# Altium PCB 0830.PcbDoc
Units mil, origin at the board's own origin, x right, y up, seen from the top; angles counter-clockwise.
Board outline 6000 x 4000 mil, 2 copper layers (Top Layer, Bottom Layer); 10 components, 22 nets, 57 pads, 0 vias.
Unrouted connection lines stored in the file: 34.
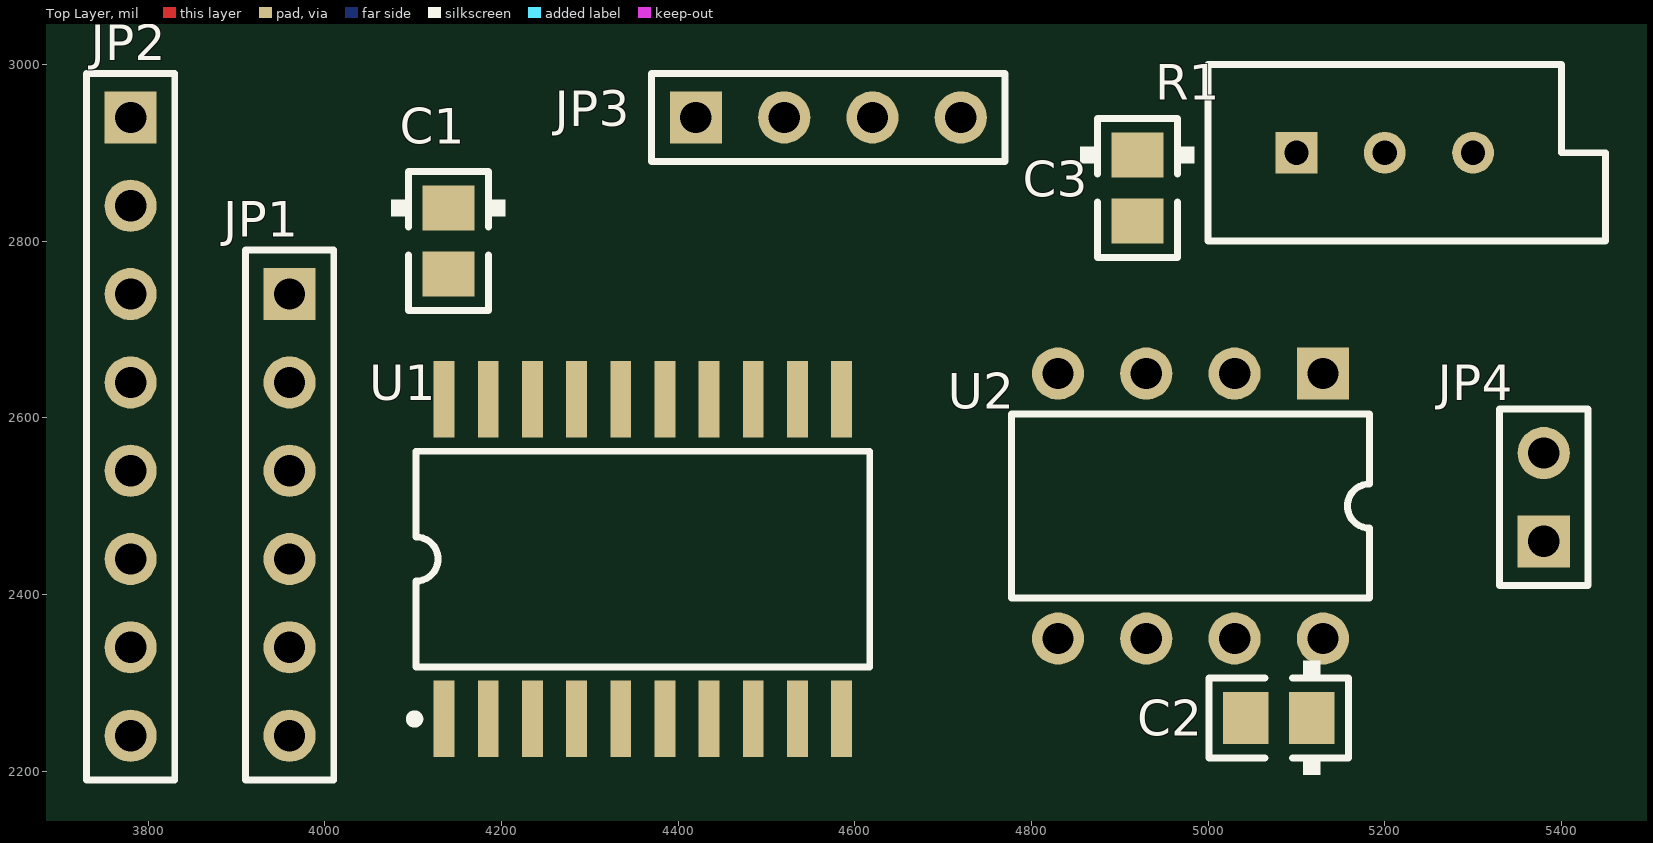
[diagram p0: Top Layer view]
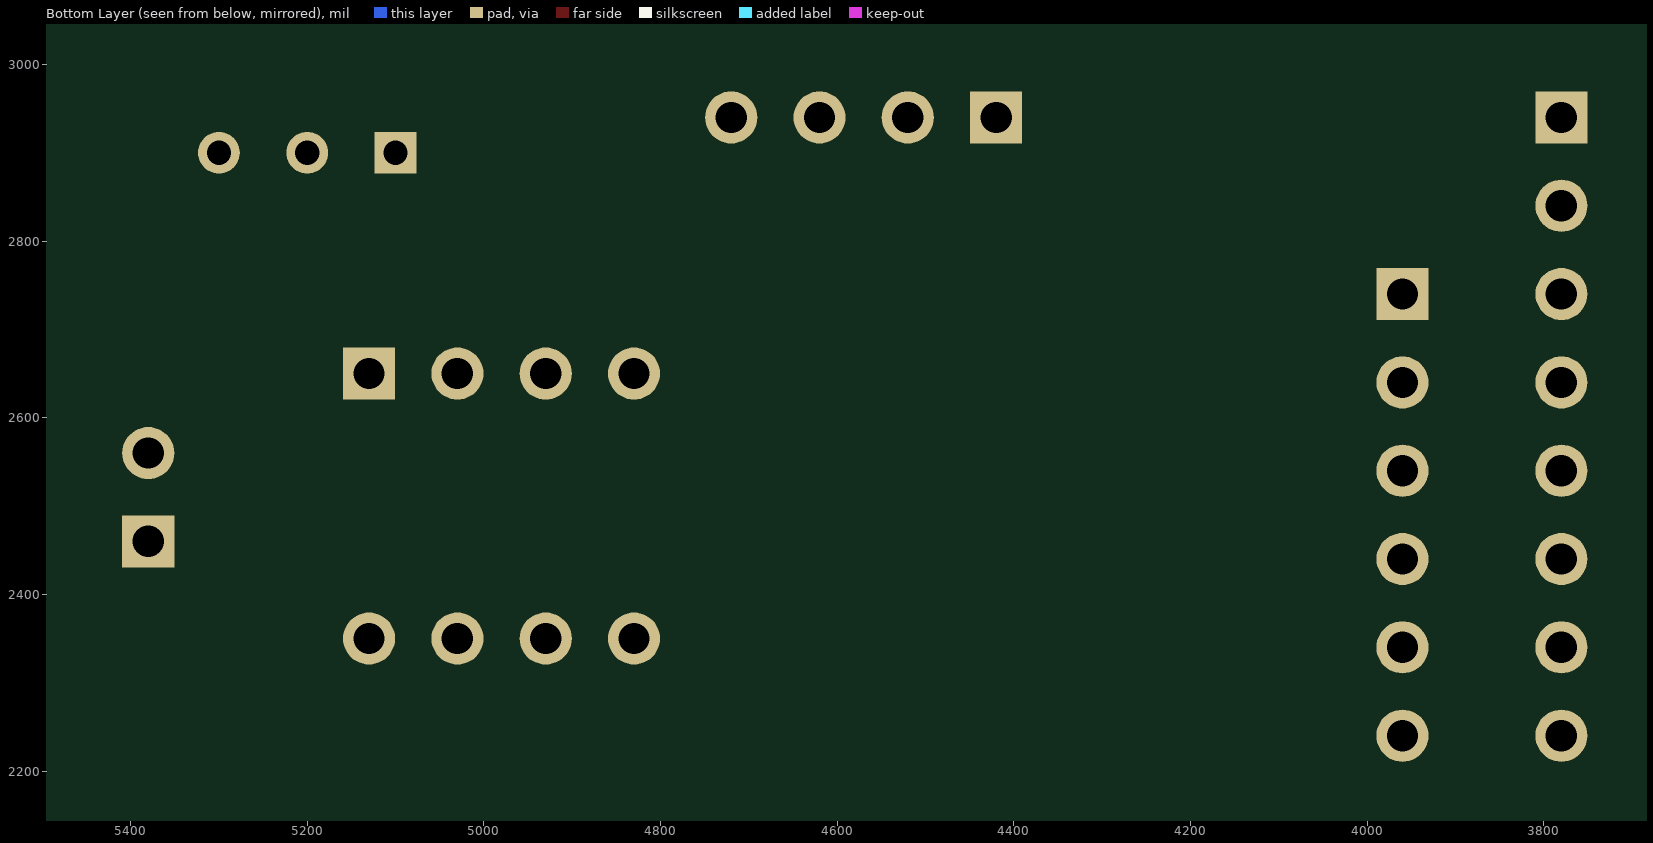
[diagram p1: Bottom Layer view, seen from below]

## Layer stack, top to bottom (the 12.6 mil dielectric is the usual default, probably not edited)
Top Layer: signal copper 1.4
Dielectric: dielectric 12.6, FR-4, Dk 4.8
Bottom Layer: signal copper 1.4

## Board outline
1000,1000 7000,1000 7000,5000 1000,5000

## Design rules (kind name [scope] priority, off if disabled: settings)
Clearance [All] p1: gap=10
ComponentClearance [All] p1: gap=10 collisioncheckmode=0
PolygonConnect [All] p1: connectstyle=Relief reliefconductorwidth=10 reliefentries=4 polygonreliefangle="90 Angle"
RoutingLayers [All] p1: top layer=Horizontal bottom layer=Vertical
RoutingVias [All] p1: holewidth=28 width=50 viastyle="Through Hole" minholewidth=28 minwidth=50 maxholewidth=28 maxwidth=50
SolderMaskExpansion [All] p1: expansion=4
TestPointUsage [All] p1: valid=0 allowmultiple=FALSE
Testpoint [All] p1: side=15 testpointundercomponent=TRUE minsize=40 maxsize=100 preferedsize=60 minholesize=0 maxholesize=40 preferedholesize=32 testpointgrid=1 style=1023 order=1234567890
Width [All] p1: maxlimit=10 minlimit=10 preferedwidth=10
16 further rules are at their usual default settings.

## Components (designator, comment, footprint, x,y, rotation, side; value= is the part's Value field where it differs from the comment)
C1 "Cap" CC2012-0805 4140,2800 r270 top
C2 "Cap" CC2012-0805 5080,2260 r180 top
C3 "Cap" CC2012-0805 4920,2860 r270 top
JP1 "Header 6" HDR1X6 3960,2740 r270 top
JP2 "Header 8" HDR1X8 3780,2940 r270 top
JP3 "Header 4" HDR1X4 4420,2940 r0 top
JP4 "Header 2" HDR1X2 5380,2460 r90 top
R1 "10K" VR5 5200,2900 r0 top
U1 "DAC0830LCM" SO-G20 4360,2440 r0 top
U2 "LF351N" DIP-8 4980,2500 r180 top

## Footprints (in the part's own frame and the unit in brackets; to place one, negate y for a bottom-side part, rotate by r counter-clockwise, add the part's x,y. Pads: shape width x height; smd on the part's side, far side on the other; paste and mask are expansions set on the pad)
CC2012-0805 [mm]
  rect 1.3x1.5 smd: 1(-0.95,0) 2(0.95,0)
  silkscreen extent -2,-1.65 2,1.64
DIP-8 [mm]
  rect 1.5x1.5 hole 0.9: 1(-3.81,-3.81)
  round 1.5 hole 0.9: 2(-1.27,-3.81) 3(1.27,-3.81) 4(3.81,-3.81) 5(3.81,3.81) 6(1.27,3.81) 7(-1.27,3.81) 8(-3.81,3.81)
  silkscreen extent -5.15,-2.65 5.15,2.65
HDR1X2 [mm]
  rect 1.5x1.5 hole 0.9: 1(0,0)
  round 1.5 hole 0.9: 2(2.54,0)
  silkscreen extent -1.27,-1.27 3.81,1.27
HDR1X4 [mm]
  rect 1.5x1.5 hole 0.9: 1(0,0)
  round 1.5 hole 0.9: 2(2.54,0) 3(5.08,0) 4(7.62,0)
  silkscreen extent -1.27,-1.27 8.89,1.27
HDR1X6 [mm]
  rect 1.5x1.5 hole 0.9: 1(0,0)
  round 1.5 hole 0.9: 2(2.54,0) 3(5.08,0) 4(7.62,0) 5(10.16,0) 6(12.7,0)
  silkscreen extent -1.27,-1.27 13.97,1.27
HDR1X8 [mm]
  rect 1.5x1.5 hole 0.9: 1(0,0)
  round 1.5 hole 0.9: 2(2.54,0) 3(5.08,0) 4(7.62,0) 5(10.16,0) 6(12.7,0) 7(15.24,0) 8(17.78,0)
  silkscreen extent -1.27,-1.27 19.05,1.27
SO-G20 [mm]
  rect 0.6x2.2 smd: 1(-5.715,-4.6) 2(-4.445,-4.6) 3(-3.175,-4.6) 4(-1.905,-4.6) 5(-0.635,-4.6) 6(0.635,-4.6) 7(1.905,-4.6) 8(3.175,-4.6) 9(4.445,-4.6) 10(5.715,-4.6) 11(5.715,4.6) 12(4.445,4.6) 13(3.175,4.6) 14(1.905,4.6) 15(0.635,4.6) 16(-0.635,4.6) 17(-1.905,4.6) 18(-3.175,4.6) 19(-4.445,4.6) 20(-5.715,4.6)
  silkscreen extent -6.69,-4.72 6.53,3.1
VR5 [mm]
  rect 1.2x1.2 hole 0.7: 1(-2.54,0)
  round 1.2 hole 0.7: 2(0,0) 3(2.54,0)
  silkscreen extent -5.08,-2.54 6.35,2.54

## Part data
C1 C2 C3: "Capacitor"
JP1: "Header, 6-Pin"
JP2: "Header, 8-Pin"
JP3: "Header, 4-Pin"
JP4: "Header, 2-Pin"
R1: library part RPot2, "Potentiometer"
U1: "8-Bit 礟-Compatible, Double-Buffered Digital-to-Analog Converter"
U2: "Wide-Bandwidth JFET Input Operational Amplifier"

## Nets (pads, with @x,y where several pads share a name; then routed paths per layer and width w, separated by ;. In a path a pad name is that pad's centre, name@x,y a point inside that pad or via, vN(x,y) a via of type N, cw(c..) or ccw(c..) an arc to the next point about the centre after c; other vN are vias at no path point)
+15V: C1.2 C2.2 JP3.1 U1.20 U2.7
-15V: C3.2 JP3.4 R1.3 U2.4
DGND: C1.1 U1.3 U1.10
GND: C2.1 C3.1 JP3.2 JP3.3 JP4.2 U1.12 U2.3
NetJP1_1: JP1.1 U1.17
NetJP1_2: JP1.2 U1.19
NetJP1_3: JP1.3 U1.18
NetJP1_4: JP1.4 U1.2
NetJP1_5: JP1.5 U1.1
NetJP2_1: JP2.1 U1.13
NetJP2_2: JP2.2 U1.14
NetJP2_3: JP2.3 U1.15
NetJP2_4: JP2.4 U1.16
NetJP2_5: JP2.5 U1.4
NetJP2_6: JP2.6 U1.5
NetJP2_7: JP2.7 U1.6
NetJP2_8: JP2.8 U1.7
NetJP4_1: JP4.1 U1.8 U2.6
NetR1_1: R1.1 U2.5
NetR1_2: R1.2 U2.1
NetU1_11: U1.11 U2.2
VIN: JP1.6 U1.9
pads on no net: U2.8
